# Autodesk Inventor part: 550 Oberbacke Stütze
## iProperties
Shininess: 64.0
Length Units: 11269
Angle Units: 11279
Time Units: 11290
Mass Units: 11283
Length Display Precision: 3
Angle Display Precision: 2
Compacted: True
Part Number: 550 Oberbacke Stütze
Document SubType Name: Modeling
Created: 2004-05
Designer: rs-44
Manufacturer: Standard
Standards Organization: Custom
Density: 0.0
Volumn: 0.0
Area: 0.0
PropertySet Name: Model Information
Control State: 0
Master: False
Checked Out: False
Author: rs-44
Revision Number: A
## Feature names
1. Extrusion4
2. Fase1 [Chamfer]
3. Bohrung1 [Hole]
